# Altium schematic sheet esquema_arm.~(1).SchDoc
size A4
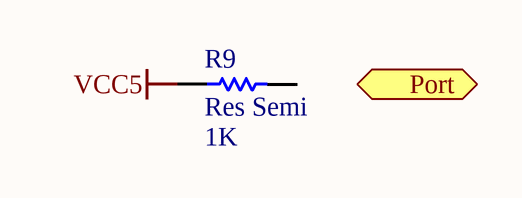
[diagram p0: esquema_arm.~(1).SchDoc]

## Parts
R9  Res Semi  value 1K  [1005[0402]]

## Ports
Port

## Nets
VCC5: R9.1

Not connected (* = marked no-connect by the designer): R9 2

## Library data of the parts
R9 = Res Semi: Semiconductor Resistor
